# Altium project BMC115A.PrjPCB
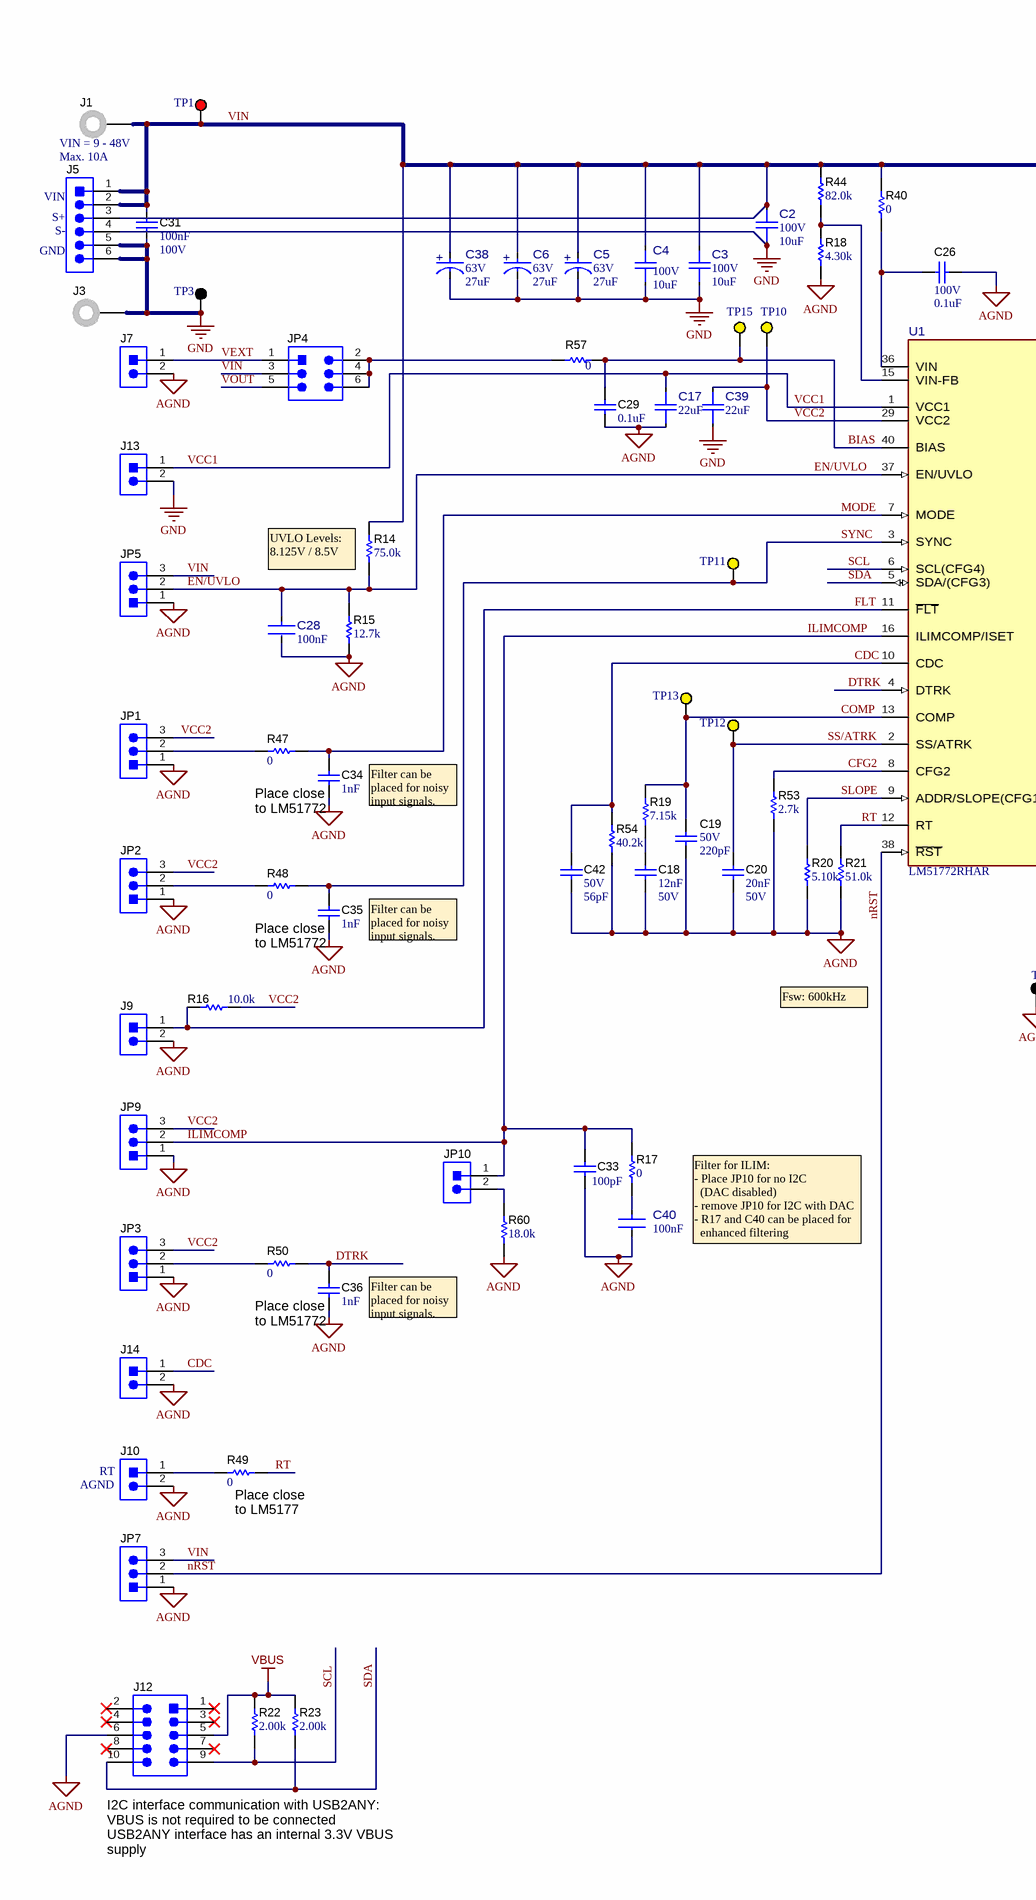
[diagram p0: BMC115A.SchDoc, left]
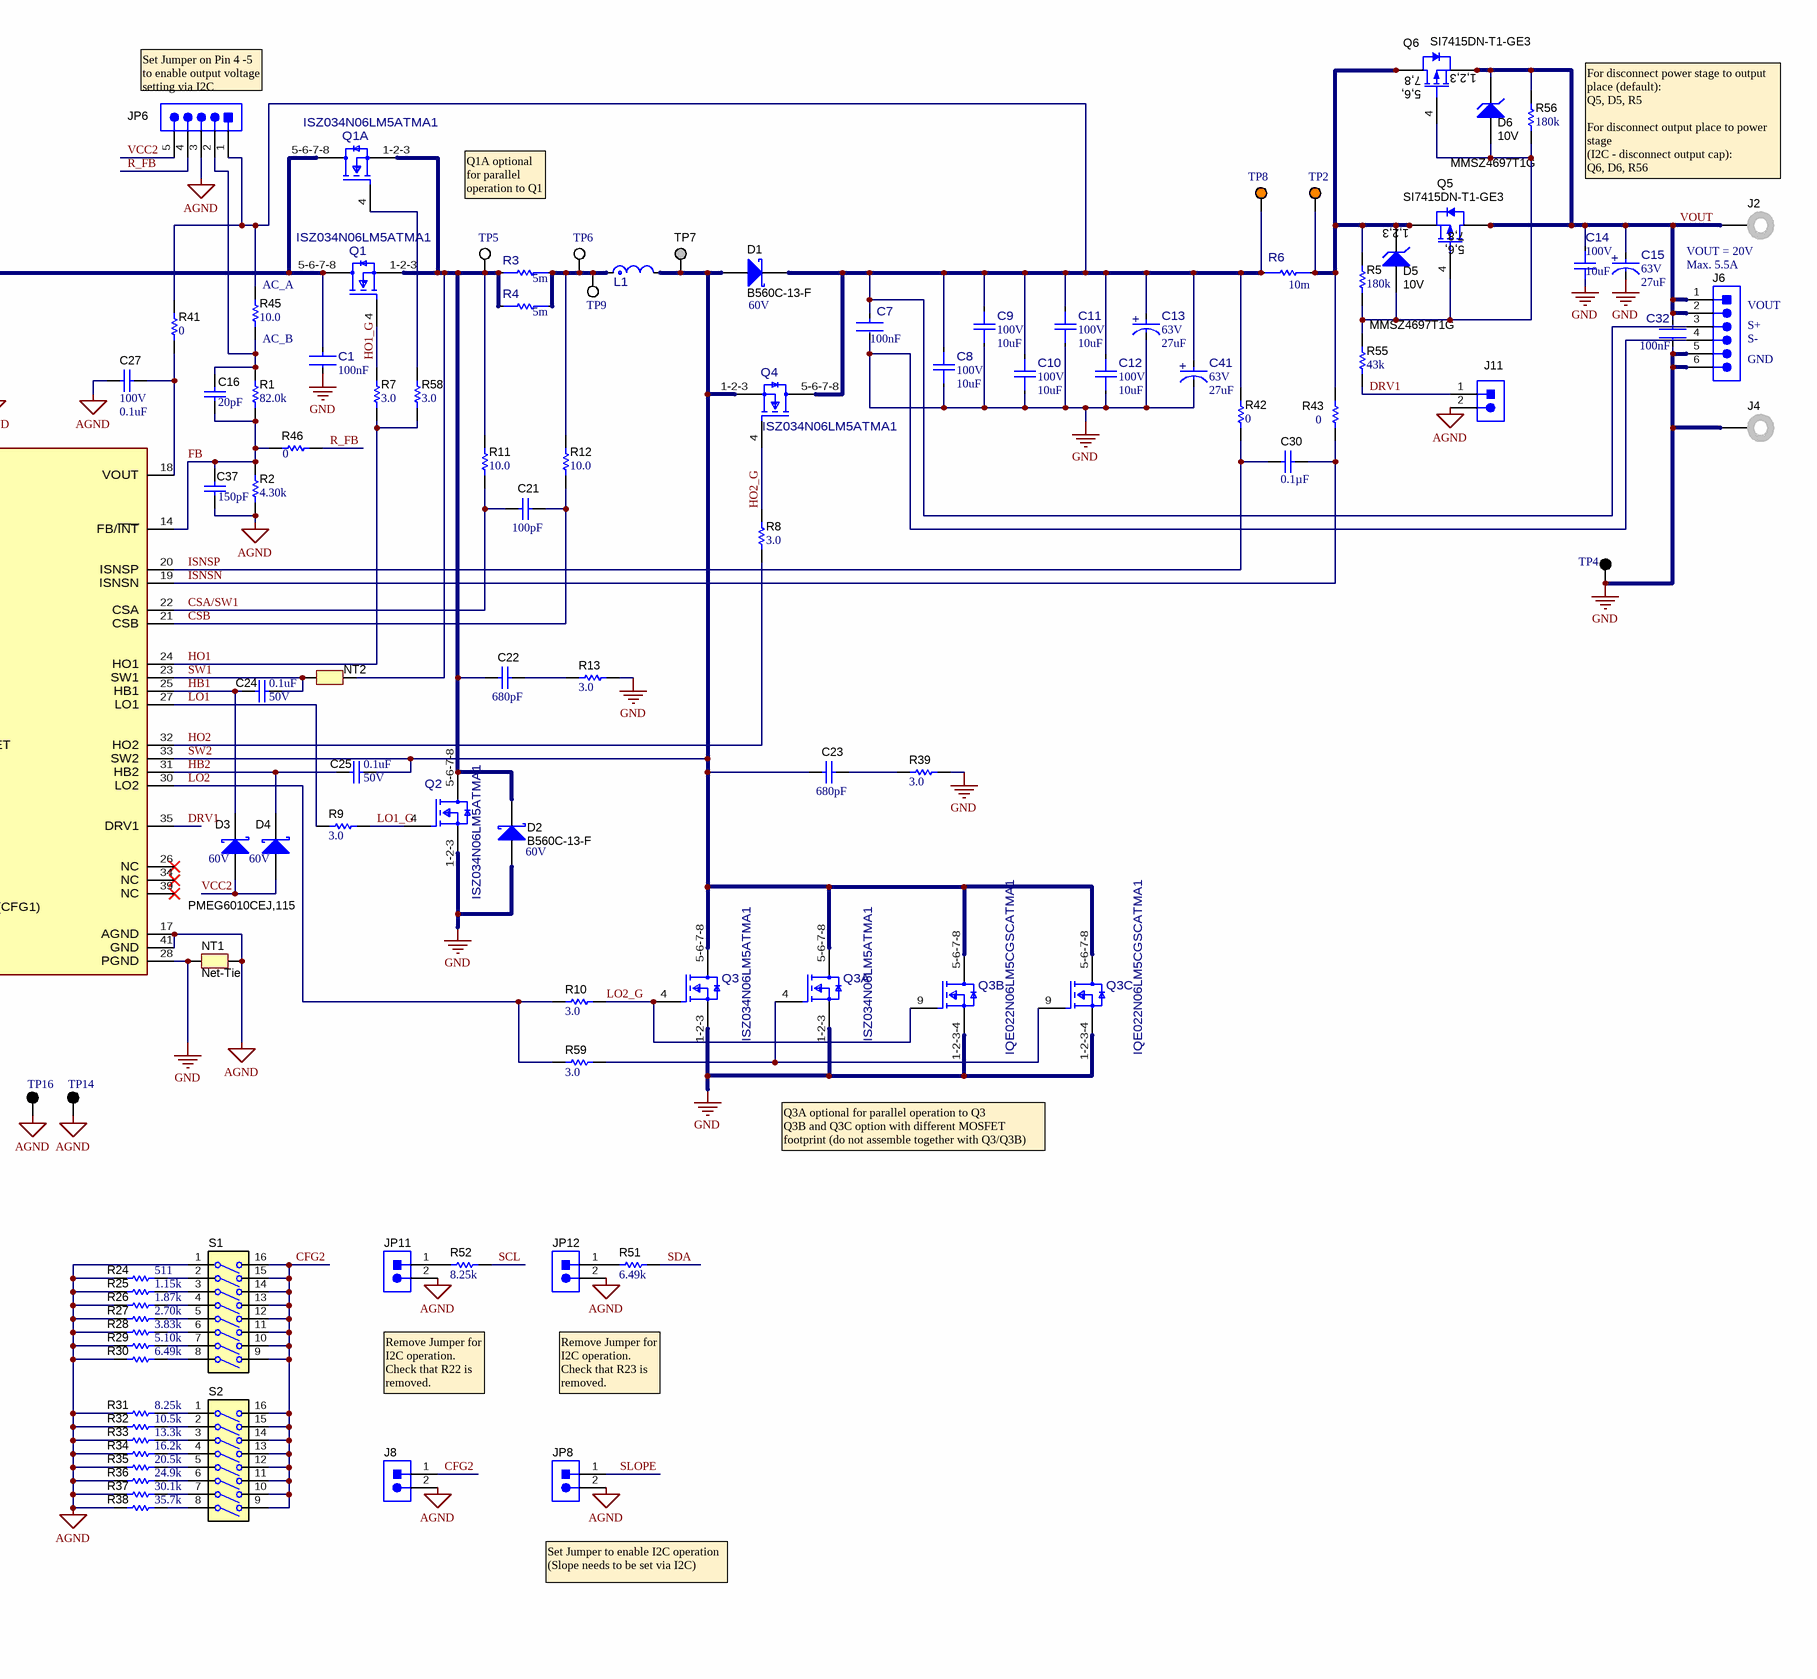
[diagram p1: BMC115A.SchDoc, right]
TID: N/A; TechSupport: http://www.ti.com/support; SCH_Rev: A; PRJ_Title: LM51772EVM-HP; PRJ_Number: BMC115; PRJ_Customer: Public Release; PCB_Rev: A; CopyrightYear: 2023
2 sheets, 200 parts. Net scope: global (net labels, ports and power ports of the same name join across sheets).
Board file: BMC115A.PcbDoc
Sheets:
  BMC115A.SchDoc
  BMC115A_Hardware.SchDoc

## Sheet BMC115A.SchDoc: LM51772RWE EVM Schematic
size 558 x 431 mm; Date: Not shown in title block; ApprovedBy: Not shown in title block; CheckedBy: Not shown in title block; Author: Not shown in title block; CompanyName: Not shown in title block; Engineer: Not shown in title block; Organization: Not shown in title block; Address1: Not shown in title block; Address2: Not shown in title block; Address3: Not shown in title block; Address4: Not shown in title block; DocumentNumber: 1; Revision: Use project parameter SCH_Rev; SheetNumber: 1; SheetTotal: 2; PageSetup: Record=PageOptions¦CenterHorizontal=True¦CenterVertical=True¦PrintScale=1.00¦XCorrection=1.00¦YCorrection=1.00¦PrintKind=0¦BorderSize=5000000¦LeftOffset=0¦BottomOffset=0¦Orientation=2¦PaperLength=1000¦PaperWidth=1000¦Scale=100¦PaperSource=15¦PrintQuality=600¦MediaType=1¦DitherType=10¦PaperKind=Letter¦PrintScaleMode=1

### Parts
C1  Cap_F: 100nF  [FP-GCM188L81H104KA57D_0603-MFG]  (hidden comment: GCM188L81H104KA57D)
C2  VDC_V: 100V  ValueDisplayed: 10uF  [FP-C3225X7R2A106K250AC_1210-MFG]  (hidden comment: C3225X7R2A106K250AC)
C3  VDC_V: 100V  ValueDisplayed: 10uF  [FP-C3225X7R2A106K250AC_1210-MFG]  (hidden comment: C3225X7R2A106K250AC)
C4  VDC_V: 100V  ValueDisplayed: 10uF  [FP-C3225X7R2A106K250AC_1210-MFG]  (hidden comment: C3225X7R2A106K250AC)
C5  VDC_V: 63V  ValueDisplayed: 27uF  [FP-A768KE276M1JLAE054_SMT_CAP_8MM3_8MM3-0]  (hidden comment: A768KE276M1JLAE054)
C6  VDC_V: 63V  ValueDisplayed: 27uF  [FP-A768KE276M1JLAE054_SMT_CAP_8MM3_8MM3-0]  (hidden comment: A768KE276M1JLAE054)
C7  Cap_F: 100nF  [FP-GCM188L81H104KA57D_0603-MFG]  (hidden comment: GCM188L81H104KA57D)
C8  VDC_V: 100V  ValueDisplayed: 10uF  [FP-C3225X7R2A106K250AC_1210-MFG]  (hidden comment: C3225X7R2A106K250AC)
C9  VDC_V: 100V  ValueDisplayed: 10uF  [FP-C3225X7R2A106K250AC_1210-MFG]  (hidden comment: C3225X7R2A106K250AC)
C10  VDC_V: 100V  ValueDisplayed: 10uF  [FP-C3225X7R2A106K250AC_1210-MFG]  (hidden comment: C3225X7R2A106K250AC)
C11  VDC_V: 100V  ValueDisplayed: 10uF  [FP-C3225X7R2A106K250AC_1210-MFG]  (hidden comment: C3225X7R2A106K250AC)
C12  VDC_V: 100V  ValueDisplayed: 10uF  [FP-C3225X7R2A106K250AC_1210-MFG]  (hidden comment: C3225X7R2A106K250AC)
C13  VDC_V: 63V  ValueDisplayed: 27uF  [FP-A768KE276M1JLAE054_SMT_CAP_8MM3_8MM3-0]  (hidden comment: A768KE276M1JLAE054)
C14  VDC_V: 100V  ValueDisplayed: 10uF  [FP-C3225X7R2A106K250AC_1210-MFG]  (hidden comment: C3225X7R2A106K250AC)
C15  VDC_V: 63V  ValueDisplayed: 27uF  [FP-A768KE276M1JLAE054_SMT_CAP_8MM3_8MM3-0]  (hidden comment: A768KE276M1JLAE054)
C16  ValueDisplayed: 20pF  [0603S]  (hidden comment: GRM1885C2A200JA01D)
C17  ValueDisplayed: 22uF  [0603S]  (hidden comment: GRT188R61A226ME13D)
C18  Cap_F: 12nF  VDC_V: 50V  [0603S]  (hidden comment: C0603C123K5RACTU)
C19  VDC_V: 50V  ValueDisplayed: 220pF  [0603S]  (hidden comment: 06035A221FAT2A)
C20  Cap_F: 20nF  VDC_V: 50V  [0603S]  (hidden comment: CC0603KRX7R9BB203)
C21  ValueDisplayed: 100pF  [0603S]  (hidden comment: GCM1885C1H101JA16J)
C22  ValueDisplayed: 680pF  [0805_HV1]  (hidden comment: GRM2195C2A681JA01D)
C23  ValueDisplayed: 680pF  [0805_HV1]  (hidden comment: GRM2195C2A681JA01D)
C24  VDC_V: 50V  ValueDisplayed: 0.1uF  [0402S]  (hidden comment: GCM155R71H104KE02D)
C25  VDC_V: 50V  ValueDisplayed: 0.1uF  [0402S]  (hidden comment: GCM155R71H104KE02D)
C26  VDC_V: 100V  ValueDisplayed: 0.1uF  [0402S]  (hidden comment: GRM155R62A104KE14D)
C27  VDC_V: 100V  ValueDisplayed: 0.1uF  [0402S]  (hidden comment: GRM155R62A104KE14D)
C28  Cap_F: 100nF  [FP-GCM188L81H104KA57D_0603-MFG]  (hidden comment: GCM188L81H104KA57D)
C29  ValueDisplayed: 0.1uF  [0603S]  (hidden comment: CGA3E3X7S2A104K080AB)
C30  ValueDisplayed: 0.1µF  [0402S]  (hidden comment: 0402BB104KW500)
C31  Cap_F: 100nF  VDC_V: 100V  [0603]  (hidden comment: GCJ188R72A104KA01D)
C32  Cap_F: 100nF  [FP-GCM188L81H104KA57D_0603-MFG]  (hidden comment: GCM188L81H104KA57D)
C33  ValueDisplayed: 100pF  [0603S]  (hidden comment: 06035A101FAT2A)
C34  Cap_F: 1nF  [0603S]  (hidden comment: 06031C102JAT2A)
C35  Cap_F: 1nF  [0603S]  (hidden comment: 06031C102JAT2A)
C36  Cap_F: 1nF  [0603S]  (hidden comment: 06031C102JAT2A)
C37  ValueDisplayed: 150pF  [0603S]  (hidden comment: GRM1885C1H151JA01D)
C38  VDC_V: 63V  ValueDisplayed: 27uF  [FP-A768KE276M1JLAE054_SMT_CAP_8MM3_8MM3-0]  (hidden comment: A768KE276M1JLAE054)
C39  ValueDisplayed: 22uF  [0603S]  (hidden comment: GRT188R61A226ME13D)
C40  Cap_F: 100nF  [FP-GCM188L81H104KA57D_0603-MFG]  (hidden comment: GCM188L81H104KA57D)
C41  VDC_V: 63V  ValueDisplayed: 27uF  [FP-A768KE276M1JLAE054_SMT_CAP_8MM3_8MM3-0]  (hidden comment: A768KE276M1JLAE054)
C42  VDC_V: 50V  ValueDisplayed: 56pF  [0603S]  (hidden comment: 06035A560FAT2A)
D1  B560C-13-F  value 60V  [SMC]
D2  B560C-13-F  value 60V  [SMC]
D3  value 60V  [SOD-323F]  (hidden comment: PMEG6010CEJ,115)
D4  PMEG6010CEJ,115  value 60V  [SOD-323F]
D5  MMSZ4697T1G  value 10V  [SOD-123]
D6  MMSZ4697T1G  value 10V  [SOD-123]
J1  108-0740-001  [Johnson_108-0740-001]  (value not drawn)
J2  108-0740-001  [Johnson_108-0740-001]  (value not drawn)
J3  108-0740-001  [Johnson_108-0740-001]  (value not drawn)
J4  108-0740-001  [Johnson_108-0740-001]  (value not drawn)
J5  61300611121  [WURTH_61300611121]  (value not drawn)
J6  61300611121  [WURTH_61300611121]  (value not drawn)
J7  61300211121  [WURTH_61300211121]  (value not drawn)
J8  61300211121  [WURTH_61300211121]  (value not drawn)
J9  61300211121  [WURTH_61300211121]  (value not drawn)
J10  61300211121  [WURTH_61300211121]  (value not drawn)
J11  61300211121  [WURTH_61300211121]  (value not drawn)
J12  N2510-6002-RB  [CONN_2510-6002]  (value not drawn)
J13  61300211121  [WURTH_61300211121]  (value not drawn)
J14  61300211121  [WURTH_61300211121]  (value not drawn)
JP1  61300311121  [WURTH_61300311121]  (value not drawn)
JP2  61300311121  [WURTH_61300311121]  (value not drawn)
JP3  61300311121  [WURTH_61300311121]  (value not drawn)
JP4  HTSW-103-07-G-D  [Samtec_HTSW-103-07-x-D]  (value not drawn)
JP5  61300311121  [WURTH_61300311121]  (value not drawn)
JP6  61300511121  [Wurth_61300511121]  (value not drawn)
JP7  61300311121  [WURTH_61300311121]  (value not drawn)
JP8  61300211121  [WURTH_61300211121]  (value not drawn)
JP9  61300311121  [WURTH_61300311121]  (value not drawn)
JP10  61300211121  [WURTH_61300211121]  (value not drawn)
JP11  61300211121  [WURTH_61300211121]  (value not drawn)
JP12  61300211121  [WURTH_61300211121]  (value not drawn)
L1  XGL1060-332MEC  [FP-XGL1060-332MEC_SMT2_10MM0_11MM3-MFG]  (value not drawn)
NT1  Net-Tie  [Net-Tie_10mil]  (net tie, no BOM)
NT2  Net-Tie  [Net-Tie_20milWide_60milLong]  (value not drawn)  (net tie, no BOM)
Q1  ISZ034N06LM5ATMA1  [FP-ISZ034N06LM5ATMA1_TSDSON8-MFG]
Q1A  ISZ034N06LM5ATMA1  [FP-ISZ034N06LM5ATMA1_TSDSON8-MFG]
Q2  ISZ034N06LM5ATMA1  [FP-ISZ034N06LM5ATMA1_TSDSON8-MFG]
Q3  ISZ034N06LM5ATMA1  [FP-ISZ034N06LM5ATMA1_TSDSON8-MFG]
Q3A  ISZ034N06LM5ATMA1  [FP-ISZ034N06LM5ATMA1_TSDSON8-MFG]
Q3B  IQE022N06LM5CGSCATMA1  [FP-IQE022N06LM5CGSCATMA1_PG-WHTFN-9-MFG]
Q3C  IQE022N06LM5CGSCATMA1  [FP-IQE022N06LM5CGSCATMA1_PG-WHTFN-9-MFG]
Q4  ISZ034N06LM5ATMA1  [FP-ISZ034N06LM5ATMA1_TSDSON8-MFG]
Q5  SI7415DN-T1-GE3  [PowerPAK_1212-8]
Q6  SI7415DN-T1-GE3  [PowerPAK_1212-8]
R1  ValueDisplayed: 82.0k  [0603S]  (hidden comment: RC0603FR-0782KL)
R2  ValueDisplayed: 4.30k  [0603S]  (hidden comment: RC0603FR-074K3L)
R3  value 5m  [FP-KRL2012E-M-R005-F-T5_0805_WIDE-MFG]  (hidden comment: KRL2012E-M-R005-F-T5)
R4  value 5m  [FP-KRL2012E-M-R005-F-T5_0805_WIDE-MFG]  (hidden comment: KRL2012E-M-R005-F-T5)
R5  ValueDisplayed: 180k  [0603S]  (hidden comment: CRCW0603180KJNEA)
R6  value 10m  [FP-KRL2012E-C-R010-F-T05_0508-MFG]  (hidden comment: KRL2012E-C-R010-F-T05)
R7  ValueDisplayed: 3.0  [0603S]  (hidden comment: CRCW06033R00JNEA)
R8  ValueDisplayed: 3.0  [0603S]  (hidden comment: CRCW06033R00JNEA)
R9  ValueDisplayed: 3.0  [0603S]  (hidden comment: CRCW06033R00JNEA)
R10  ValueDisplayed: 3.0  [0603S]  (hidden comment: CRCW06033R00JNEA)
R11  ValueDisplayed: 10.0  [0603S]  (hidden comment: CRCW060310R0FKEAHP)
R12  ValueDisplayed: 10.0  [0603S]  (hidden comment: CRCW060310R0FKEAHP)
R13  ValueDisplayed: 3.0  [0603S]  (hidden comment: CRCW06033R00JNEA)
R14  ValueDisplayed: 75.0k  [0603S]  (hidden comment: RC0603FR-0775KL)
R15  ValueDisplayed: 12.7k  [0603S]  (hidden comment: RC0603FR-0712K7L)
R16  ValueDisplayed: 10.0k  [0603S]  (hidden comment: RT0603BRD0710KL)
R17  ValueDisplayed: 0  [0603S]  (hidden comment: RMCF0603ZT0R00)
R18  ValueDisplayed: 4.30k  [0603S]  (hidden comment: RC0603FR-074K3L)
R19  ValueDisplayed: 7.15k  [0603S]  (hidden comment: CRCW06037K15FKEA)
R20  ValueDisplayed: 5.10k  [0603S]  (hidden comment: RC0603FR-075K1L)
R21  ValueDisplayed: 51.0k  [0603S]  (hidden comment: RC0603FR-0751KL)
R22  ValueDisplayed: 2.00k  [0603S]  (hidden comment: RC0603FR-072KL)
R23  ValueDisplayed: 2.00k  [0603S]  (hidden comment: RC0603FR-072KL)
R24  ValueDisplayed: 511  [0603S]  (hidden comment: CRCW0603511RFKEA)
R25  ValueDisplayed: 1.15k  [0603S]  (hidden comment: CRCW06031K15FKEA)
R26  ValueDisplayed: 1.87k  [0603S]  (hidden comment: RC0603FR-071K87L)
R27  ValueDisplayed: 2.70k  [0603S]  (hidden comment: RC0603FR-072K7L)
R28  ValueDisplayed: 3.83k  [0603S]  (hidden comment: CRCW06033K83FKEA)
R29  ValueDisplayed: 5.10k  [0603S]  (hidden comment: RC0603FR-075K1L)
R30  ValueDisplayed: 6.49k  [0603S]  (hidden comment: RC0603FR-076K49L)
R31  ValueDisplayed: 8.25k  [0603S]  (hidden comment: RC0603FR-078K25L)
R32  ValueDisplayed: 10.5k  [0603S]  (hidden comment: CRCW060310K5FKEA)
R33  ValueDisplayed: 13.3k  [0603S]  (hidden comment: RC0603FR-0713K3L)
R34  ValueDisplayed: 16.2k  [0603S]  (hidden comment: CRCW060316K2FKEA)
R35  ValueDisplayed: 20.5k  [0603S]  (hidden comment: RC0603FR-0720K5L)
R36  ValueDisplayed: 24.9k  [0603S]  (hidden comment: CRCW060324K9FKEA)
R37  ValueDisplayed: 30.1k  [0603S]  (hidden comment: CRCW060330K1FKEA)
R38  ValueDisplayed: 35.7k  [0603S]  (hidden comment: CRCW060335K7FKEA)
R39  ValueDisplayed: 3.0  [0603S]  (hidden comment: CRCW06033R00JNEA)
R40  ValueDisplayed: 0  [0603S]  (hidden comment: RMCF0603ZT0R00)
R41  ValueDisplayed: 0  [0603S]  (hidden comment: RMCF0603ZT0R00)
R42  ValueDisplayed: 0  [0603S]  (hidden comment: RMCF0603ZT0R00)
R43  ValueDisplayed: 0  [0603S]  (hidden comment: RMCF0603ZT0R00)
R44  ValueDisplayed: 82.0k  [0603S]  (hidden comment: RC0603FR-0782KL)
R45  ValueDisplayed: 10.0  [0603S]  (hidden comment: RC0603FR-0710RL)
R46  ValueDisplayed: 0  [0603S]  (hidden comment: RMCF0603ZT0R00)
R47  ValueDisplayed: 0  [0603S]  (hidden comment: RMCF0603ZT0R00)
R48  ValueDisplayed: 0  [0603S]  (hidden comment: RMCF0603ZT0R00)
R49  ValueDisplayed: 0  [0603S]  (hidden comment: RMCF0603ZT0R00)
R50  ValueDisplayed: 0  [0603S]  (hidden comment: RMCF0603ZT0R00)
R51  ValueDisplayed: 6.49k  [0603S]  (hidden comment: RC0603FR-076K49L)
R52  ValueDisplayed: 8.25k  [0603S]  (hidden comment: RC0603FR-078K25L)
R53  ValueDisplayed: 2.7k  [0603S]  (hidden comment: CRCW06032K70JNEA)
R54  ValueDisplayed: 40.2k  [0603S]  (hidden comment: CRCW060340K2FKEA)
R55  ValueDisplayed: 43k  [0603S]  (hidden comment: CRCW060343K0JNEA)
R56  ValueDisplayed: 180k  [0603S]  (hidden comment: CRCW0603180KJNEA)
R57  ValueDisplayed: 0  [0603S]  (hidden comment: RMCF0603ZT0R00)
R58  ValueDisplayed: 3.0  [0603S]  (hidden comment: CRCW06033R00JNEA)
R59  ValueDisplayed: 3.0  [0603S]  (hidden comment: CRCW06033R00JNEA)
R60  ValueDisplayed: 18.0k  [0603S]  (hidden comment: RC0603FR-0718KL)
S1  218-8LPST  [SW_218-8LP]  (value not drawn)
S2  218-8LPST  [SW_218-8LP]  (value not drawn)
TP1  5010  [Keystone5010]  (value not drawn)
TP2  5013  [Keystone5013]  (value not drawn)
TP3  5011  [Keystone5011]  (value not drawn)
TP4  5011  [Keystone5011]  (value not drawn)
TP5  5012  [Keystone5012]  (value not drawn)
TP6  5012  [Keystone5012]  (value not drawn)
TP7  5128  [Keystone5128]  (value not drawn)
TP8  5013  [Keystone5013]  (value not drawn)
TP9  5012  [Keystone5012]  (value not drawn)
TP10  5004  [Keystone5004]  (value not drawn)
TP11  5004  [Keystone5004]  (value not drawn)
TP12  5004  [Keystone5004]  (value not drawn)
TP13  5004  [Keystone5004]  (value not drawn)
TP14  5001  [Keystone5001]  (value not drawn)
TP15  5004  [Keystone5004]  (value not drawn)
TP16  5001  [Keystone5001]  (value not drawn)
U1  LM51772RHAR  [RHA0040P-MFG]

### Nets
AGND: C17.1 C18.2 C19.2 C20.2 C26.1 C27.2 C28.2 C29.1 C33.2 C34.2 C35.2 C36.2 C37.2 C40.2 C42.2 J7.2 J8.2 J9.2 J10.2 J11.2 J12.6 J14.2 JP1.1 JP2.1 JP3.1 JP5.1 JP6.3 JP7.1 JP8.2 JP9.1 JP11.2 JP12.2 NT1.2 R2.1 R15.1 R18.1 R20.1 R21.1 R24.1 R25.1 R26.1 R27.1 R28.1 R29.1 R30.1 R31.1 R32.1 R33.1 R34.1 R35.1 R36.1 R37.1 R38.1 R53.1 R54.1 R60.1 S1.1 TP14.1 TP16.1 U1.17(AGND) U1.41(GND)
GND: C1.2 C2.1 C3.1 C4.1 C5.1(CATHODE) C6.1(CATHODE) C7.2 C8.1 C9.1 C10.1 C11.1 C12.1 C13.1(CATHODE) C14.1 C15.1(CATHODE) C31.2 C32.2 C38.1(CATHODE) C39.1 C41.1(CATHODE) D2.2(A) J3.1 J4.1 J5.4 J5.5 J5.6 J6.4 J6.5 J6.6 J13.2 NT1.1 Q2.1-2-3(S) Q3.1-2-3(S) Q3A.1-2-3(S) Q3B.1-2-3-4(Source) Q3C.1-2-3-4(Source) R13.1 R39.1 TP3.1 TP4.1 U1.28(PGND)
VBUS: J12.5 R22.2 R23.2
BIAS: C29.2 R57.1 TP15.1 U1.40(BIAS)
CDC: C42.1 J14.1 R54.2 U1.10(CDC)
CFG2: J8.1 R53.2 S1.9(8A) S1.10(7A) S1.11(6A) S1.12(5A) S1.13(4A) S1.14(3A) S1.15(2A) S1.16(1A) S2.9(8A) S2.10(7A) S2.11(6A) S2.12(5A) S2.13(4A) S2.14(3A) S2.15(2A) S2.16(1A) U1.8(CFG2)
COMP: C19.1 R19.2 TP13.1 U1.13(COMP)
CSA/SW1: C21.2 R11.1 U1.22(CSA)
CSB: C21.1 R12.1 U1.21(CSB)
DRV1: J11.1 R55.1 U1.35(DRV1)
DTRK: C36.1 R50.2 U1.4(DTRK)
EN/UVLO: C28.1 JP5.2 R14.1 R15.2 U1.37(EN/UVLO)
FB: C16.2 C37.1 R1.1 R2.2 R46.1 U1.14(FB/~{INT})
FLT: J9.1 R16.1 U1.11(~{FLT})
HB1: C24.2 D3.1(K) U1.25(HB1)
HB2: C25.2 D4.1(K) U1.31(HB2)
HO1: R7.1 R58.1 U1.24(HO1)
HO1_G: Q1.4(G) R7.2
HO2: R8.1 U1.32(HO2)
HO2_G: Q4.4(G) R8.2
ILIMCOMP: C33.1 JP9.2 JP10.1 R17.2 U1.16(ILIMCOMP/ISET)
ISNSN: C30.1 R43.1 U1.19(ISNSN)
ISNSP: C30.2 R42.1 U1.20(ISNSP)
LO1: R9.2 U1.27(LO1)
LO1_G: Q2.4(G) R9.1
LO2: R10.2 R59.2 U1.30(LO2)
LO2_G: Q3.4(G) Q3B.9(Gate) R10.1
MODE: C34.1 R47.2 U1.7(MODE)
nRST: JP7.2 U1.38(~{RST})
R_FB: JP6.4 R46.2
RT: R21.2 R49.1 U1.12(RT)
SCL: J12.9 R22.1 R52.2 U1.6(SCL(CFG4))
SDA: J12.10 R23.1 R51.2 U1.5(SDA/(CFG3))
SLOPE: JP8.1 R20.2 U1.9(ADDR/SLOPE(CFG1))
SS/ATRK: C20.1 TP12.1 U1.2(SS/ATRK)
SW1: C24.1 NT2.1 U1.23(SW1)
SW2: C23.2 C25.1 D1.2(A) L1.2 Q3.5-6-7-8(D) Q3A.5-6-7-8(D) Q3B.5-6-7-8(Drain) Q3C.5-6-7-8(Drain) Q4.1-2-3(S) TP7.1 U1.33(SW2)
SYNC: C35.1 R48.2 TP11.1 U1.3(SYNC)
VCC1: C17.2 J13.1 U1.1(VCC1)
VCC2: C39.2 D3.2(A) D4.2(A) JP1.3 JP2.3 JP3.3 JP6.5 JP9.3 R16.2 TP10.1 U1.29(VCC2)
VEXT: J7.1 JP4.1
VIN: C1.1 C2.2 C3.2 C4.2 C5.2(ANODE) C6.2(ANODE) C31.1 C38.2(ANODE) J1.1 J5.1 J5.2 J5.3 JP4.3 JP5.3 JP7.3 Q1.5-6-7-8(D) Q1A.5-6-7-8(D) R14.2 R40.2 R44.2 TP1.1
VOUT: C14.2 C15.2(ANODE) C32.1 D6.1(K) J2.1 J6.1 J6.2 JP4.5 Q5.5(D) Q5.6(D) Q5.7(D) Q5.8(D) Q5.9(D) Q6.1(S) Q6.2(S) Q6.3(S) R56.2
NetC7_1: C7.1 C8.2 C9.2 C10.2 C11.2 C12.2 C13.2(ANODE) C41.2(ANODE) D1.1(K) J6.3 JP6.1 Q4.5-6-7-8(D) R6.1 R41.2 R42.2 R45.2 TP8.1
NetC16_1: C16.1 JP6.2 R1.2 R45.1
NetC18_1: C18.1 R19.1
NetC22_1: C22.1 R13.2
NetC22_2: C22.2 D2.1(K) NT2.2 Q1.1-2-3(S) Q1A.1-2-3(S) Q2.5-6-7-8(D) R3.2 R4.2 R11.2 TP5.1
NetC23_1: C23.1 R39.2
NetC26_2: C26.2 R40.1 U1.36(VIN)
NetC27_1: C27.1 R41.1 U1.18(VOUT)
NetC40_1: C40.1 R17.1
NetD5_1: D5.1(K) Q5.1(S) Q5.2(S) Q5.3(S) Q6.5(D) Q6.6(D) Q6.7(D) Q6.8(D) Q6.9(D) R5.2 R6.2 R43.2 TP2.1
NetD5_2: D5.2(A) D6.2(A) Q5.4(G) Q6.4(G) R5.1 R55.2 R56.1
NetJ10_1: J10.1 R49.2
NetJP1_2: JP1.2 R47.1
NetJP2_2: JP2.2 R48.1
NetJP3_2: JP3.2 R50.1
NetJP4_2: JP4.2 JP4.4 JP4.6 R57.2
NetJP10_2: JP10.2 R60.2
NetJP11_1: JP11.1 R52.1
NetJP12_1: JP12.1 R51.1
NetL1_1: L1.1 R3.1 R4.1 R12.2 TP6.1 TP9.1
NetQ1A_4: Q1A.4(G) R58.2
NetQ3A_4: Q3A.4(G) Q3C.9(Gate) R59.1
NetR18_2: R18.2 R44.1 U1.15(VIN-FB)
NetR24_2: R24.2 S1.2
NetR25_2: R25.2 S1.3
NetR26_2: R26.2 S1.4
NetR27_2: R27.2 S1.5
NetR28_2: R28.2 S1.6
NetR29_2: R29.2 S1.7
NetR30_2: R30.2 S1.8
NetR31_2: R31.2 S2.1
NetR32_2: R32.2 S2.2
NetR33_2: R33.2 S2.3
NetR34_2: R34.2 S2.4
NetR35_2: R35.2 S2.5
NetR36_2: R36.2 S2.6
NetR37_2: R37.2 S2.7
NetR38_2: R38.2 S2.8

Not connected (* = marked no-connect by the designer): J12 1* 2* 3* 4* 7* 8*; U1 26(NC)* 34(NC)* 39(NC)*

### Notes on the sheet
- (near JP6) Set Jumper on Pin 4 -5 to enable output voltage setting via I2C
- Q1A optional for parallel operation to Q1
- For disconnect power stage to output place (default):
  Q5, D5, R5
  For disconnect output place to power stage
  (I2C - disconnect output cap):
  Q6, D6, R56
- (near J1) VIN = 9 - 48V
- Max. 10A
- (near J2) VOUT = 20V
- Max. 5.5A
- (near J5) VIN
- (near J5) S+
- (near J5) S-
- (near R45) AC_A
- (near R45) AC_B
- (near J6) VOUT
- (near J6) S+
- (near J6) S-
- (near J5) GND
- (near J6) GND
- (near R14) UVLO Levels:
  8.125V / 8.5V
- (near C34) Place close
  to LM51772
- (near C34) Filter can be placed for noisy input signals.
- (near C35) Place close
  to LM51772
- (near C35) Filter can be placed for noisy input signals.
- Fsw: 600kHz
- Q3A optional for parallel operation to Q3
  Q3B and Q3C option with different MOSFET footprint (do not assemble together with Q3/Q3B)
- Filter for ILIM:
  - Place JP10 for no I2C
  (DAC disabled)
  - remove JP10 for I2C with DAC
  - R17 and C40 can be placed for
  enhanced filtering
- Filter can be placed for noisy input signals.
- Remove Jumper for I2C operation.
  Check that R22 is removed.
- Remove Jumper for I2C operation.
  Check that R23 is removed.
- (near C36) Place close
  to LM51772
- (near J10) AGND
- (near J10) RT
- (near R49) Place close
  to LM5177
- Set Jumper to enable I2C operation
  (Slope needs to be set via I2C)
- (near J12) I2C interface communication with USB2ANY:
  VBUS is not required to be connected
  USB2ANY interface has an internal 3.3V VBUS supply

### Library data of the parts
C1 C7 C28 C32 C40 = CMP-0086535-1: 0.1µF ±10% 50V Ceramic Capacitor X8L 0603 (1608 Metric); Manufacturer: Murata Electronics North America; Symbol Name: SYM-GCM188L81H104KA57D; AEC Qualified: Yes; TempCo: -40+15%; SizeZ_mm: 0.9mm; AEC Grade: Grade 0
C2-C4 C8-C12 C14 = CMP-0096021-1: 10 µF ±10% 100V Ceramic Capacitor X7R 1210 (3225 Metric); Manufacturer: TDK; Cap_F: 10µF; AEC Qualified: No; Value: 10µF; SizeZ_mm: 2.85mm; TempCo: 15%
C5 C6 C13 C15 C38 C41 = CMP-0097690-1: Cap Aluminum Polymer 27uF 63V 20% Solder Cylindrical 54m Ohm 1175mA 2000 hr 125°C T/R; Manufacturer: KEMET; Life: 2000Hours; Cap_F: 27µF; Value: 27µF; Leakage Current: 340uA; SizeZ_mm: 7mm; IRMS_A: 1.175A; AEC Qualified: No
C16 = CMP-0007253-4: CAP, CERM, 20 pF, 100 V, +/- 5%, C0G/NP0, 0603; Manufacturer: MuRata; TaMin_C: -55°C; Polarized: N; SizeAreaWB_mm2: 4.68; Value1: Unknown; U/M: EA; Value: 20pF; TaMax_C: 125°C; SizeZ_mm: 1; SizeX_mm: 1.6; SizeY_mm: 0.8; Cap_Case: 0603; Value2: 100V; SizeArea_mm2: 1.28; AEC Category: Q200
C17 C39 = CMP-0092433-2: Multi-Layer Ceramic Capacitor 22uF 10V X5R ±20% 0603 Paper T/R; Manufacturer: Murata; Cap_F: 22µF; Value: 22µF; SizeZ_mm: 1mm; AEC Qualified: Yes; AEC Grade: Grade 3; TempCo: 15%
C18 = CMP-0084236-1: CAP, CERM, 0.012 µF, 50 V,+/- 10%, X7R, AEC-Q200 Grade 1, 0603; Manufacturer: Kemet; TaMin_C: -55°C; Polarized: N; SizeAreaWB_mm2: 4.68; U/M: EA; Value: 0.012uF; TaMax_C: 125°C; SizeZ_mm: 1; SizeX_mm: 1.6; SizeY_mm: 0.8; Cap_Case: 0603; SizeArea_mm2: 1.28; AEC Qualified: Y; AEC Category: Q200
C19 = CMP-0006776-4: CAP, CERM, 220 pF, 50 V, +/- 1%, C0G/NP0, 0603; Manufacturer: AVX; TaMin_C: -55°C; ESR_ohm: 83m; Polarized: N; SizeAreaWB_mm2: 4.68; Value1: 0.083 ohm; U/M: EA; Value: 220pF; TaMax_C: 125°C; SizeZ_mm: 1; SizeX_mm: 1.6; SizeY_mm: 0.8; Cap_Case: 0603; SizeArea_mm2: 1.28; AEC Category: Q200
C20 = CMP-0086295-1: CAP, CERM, 0.02 µF, 50 V,+/- 10%, X7R, 0603; Manufacturer: Yageo; SizeX_mm: 1.6; SizeAreaWB_mm2: 4.68; TaMin_C: -55°C; SizeZ_mm: 1; SizeArea_mm2: 1.28; U/M: EA; Value: 0.02uF; Polarized: N; SizeY_mm: 0.8; TaMax_C: 125°C; Cap_Case: 0603; AEC Category: Q200; ValueDisplayed: 0.02µF
C21 = CMP-0750041-1: CAP, CERM, 100 pF, 50 V,+/- 5%, C0G/NP0, AEC-Q200 Grade 1, 0603; Manufacturer: MuRata; AEC Grade: 1; SizeArea_mm2: 1.28; SizeX_mm: 1.6; Polarized: N; Cap_Case: 0603; TaMax_C: 125°C; Value2: 50V; Value: 100pF; U/M: EA; AEC Qualified: Y; SizeAreaWB_mm2: 4.68; TaMin_C: -55°C; SizeY_mm: 0.8; AEC Category: Q200
C22 C23 = CMP-0008176-2: CAP, CERM, 680 pF, 100 V, +/- 5%, C0G/NP0, 0805; Manufacturer: MuRata; TaMin_C: -55°C; Polarized: N; SizeAreaWB_mm2: 6.75; Value1: Unknown; U/M: EA; Value: 680pF; TaMax_C: 125°C; SizeZ_mm: 1.45; SizeX_mm: 2; SizeY_mm: 1.25; Cap_Case: 0805; Value2: 100V; SizeArea_mm2: 2.5; AEC Category: Q200
C24 C25 = CMP-0006356-2: CAP, CERM, 0.1 uF, 50 V, +/- 10%, X7R, AEC-Q200 Grade 1, 0402; Manufacturer: MuRata; TaMin_C: -55°C; Polarized: N; SizeAreaWB_mm2: 3; Value1: Unknown; U/M: EA; Value: 0.1uF; TaMax_C: 125°C; SizeZ_mm: 0.6; SizeX_mm: 1; SizeY_mm: 0.5; Cap_Case: 0402; AEC Qualified: Y; Cap_F: 100nF; AEC Category: Q200
C26 C27 = CMP-0006618-2: CAP, CERM, 0.1 uF, 100 V, +/- 10%, X5R, 0402; Manufacturer: MuRata; TaMin_C: -55°C; Polarized: N; SizeAreaWB_mm2: 3; Value1: Unknown; U/M: EA; Value: 0.1uF; TaMax_C: 85°C; SizeZ_mm: 0.6; SizeX_mm: 1; SizeY_mm: 0.5; Cap_Case: 0402; Cap_F: 100nF; AEC Category: Q200
C29 = CMP-0007099-4: CAP, CERM, 0.1 uF, 100 V, +/- 10%, X7S, AEC-Q200 Grade 1, 0603; Manufacturer: TDK; TaMin_C: -55°C; ESR_ohm: 0.04959; Polarized: N; SizeAreaWB_mm2: 4.68; Value1: 0.04959 ohm; U/M: EA; Value: 0.1uF; TaMax_C: 125°C; SizeZ_mm: 1; SizeX_mm: 1.6; SizeY_mm: 0.8; Cap_Case: 0603; Value2: 100V; SizeArea_mm2: 1.28; AEC Qualified: Y; Cap_F: 100nF; IRMS_A: 7.51618dA; AEC Category: Q200
C30 = CMP-0860983-1: CAP, CERM, 0.1 µF, 50 V,+/- 10%, X7R, 0402; Manufacturer: Passive Plus; Cap_Case: 0402; TaMax_C: 125°C; VDC_V: 50V; U/M: EA; SizeY_mm: 0.5; TaMin_C: -55°C; SizeAreaWB_mm2: 3; Value: 0.1uF; AEC Qualified: N; SizeX_mm: 1; AEC Category: Q200; SizeZ_mm: 0.6; Cap_F: 100nF
C31 = CMP-0064935-4: CAP, CERM, 0.1 uF, 100 V,+/- 10%, X7R, AEC-Q200 Grade 1, 0603; Manufacturer: MuRata; TaMin_C: -55°C; Polarized: N; SizeAreaWB_mm2: 4.68; Value1: Unknown; U/M: EA; Value: 0.1uF; TaMax_C: 125°C; SizeZ_mm: 1; SizeX_mm: 1.6; SizeY_mm: 0.8; SizeArea_mm2: 1.28; AEC Qualified: Y; AEC Category: Q200
C33 = CMP-0006762-4: CAP, CERM, 100 pF, 50 V, +/- 1%, C0G/NP0, 0603; Manufacturer: AVX; TaMin_C: -55°C; Polarized: N; SizeAreaWB_mm2: 4.68; Value1: Unknown; U/M: EA; TaMax_C: 125°C; SizeZ_mm: 1; SizeX_mm: 1.6; SizeY_mm: 0.8; Cap_Case: 0603; Value2: 50V; SizeArea_mm2: 1.28; Value: 100pF; AEC Category: Q200
C34-C36 = CMP-0006723-4: CAP, CERM, 1000 pF, 100 V, +/- 5%, X7R, 0603; Manufacturer: AVX; TaMin_C: -55°C; ESR_ohm: 2.76d; Polarized: N; SizeAreaWB_mm2: 4.68; Value1: 0.276 ohm; U/M: EA; Value: 1000pF; TaMax_C: 125°C; SizeZ_mm: 1; SizeX_mm: 1.6; SizeY_mm: 0.8; Cap_Case: 0603; Value2: 100V; SizeArea_mm2: 1.28; AEC Category: Q200
C37 = CMP-0007185-4: CAP, CERM, 150 pF, 50 V, +/- 5%, C0G/NP0, 0603; Manufacturer: MuRata; TaMin_C: -55°C; Polarized: N; SizeAreaWB_mm2: 4.68; Value1: Unknown; U/M: EA; Value: 150pF; TaMax_C: 125°C; SizeZ_mm: 1; SizeX_mm: 1.6; SizeY_mm: 0.8; Cap_Case: 0603; Value2: 50V; SizeArea_mm2: 1.28; AEC Category: Q200
C42 = CMP-0006792-4: CAP, CERM, 56 pF, 50 V, +/- 1%, C0G/NP0, 0603; Manufacturer: AVX; TaMin_C: -55°C; Polarized: N; SizeAreaWB_mm2: 4.68; Value1: Unknown; U/M: EA; Value: 56pF; TaMax_C: 125°C; SizeZ_mm: 1; SizeX_mm: 1.6; SizeY_mm: 0.8; Cap_Case: 0603; SizeArea_mm2: 1.28; AEC Category: Q200
D1 D2 = CMP-0028433-2: Diode, Schottky, 60 V, 5 A, SMC; Manufacturer: Diodes Inc.; Io_A: 5A; Green_Lifecycle: Active; SizeAreaWB_mm2: 83.2686; Green_REACh: Passed; TJmax_C: 125°C; SizeZ_mm: 2.6; SizeX_mm: 8.13; SizeY_mm: 6.22; Vf_V: 700mV; Value2: 0.7V; SizeArea_mm2: 50.5686; AEC Category: Q101; RJC_CperW: 10
D3 D4 = CMP-0077011-2: Diode, Schottky, 60 V, 1 A, SOD-323F; Manufacturer: Nexperia; SizeX_mm: 2.5; TJmax_C: 150°C; SizeZ_mm: 0.8; Green_Lifecycle: Not Set; Value2: 0.66V; SizeAreaWB_mm2: 7.875; Green_REACh: Incomplete; Io_A: 1A; SizeY_mm: 1.25; SizeArea_mm2: 3.125; Vf_V: 660mV; AEC Category: Q101
D5 D6 = CMP-0005740-3: Diode, Zener, 10 V, 500 mW, SOD-123; Manufacturer: ON Semiconductor; SizeY_mm: 1.7; SizeX_mm: 3.85; RJA_CperW: 340; SizeAreaWB_mm2: 13.095; AEC Category: Q101; Power_W: 500mW; SizeZ_mm: 1.35; Value1: 0.5W; SizeArea_mm2: 6.545
J1-J4 = CMP-0055387-2: Standard Banana Jack, Uninsulated, 15A; Manufacturer: Cinch Connectivity; CNHeader: FALSE; Green_Lifecycle: Active; Green_REACh: Passed; CT: TRUE
J5 J6 = CMP-0054801-2: Header, 2.54 mm, 6x1, Gold, TH; Manufacturer: Wurth Elektronik; Cert_UL: Y; Gender: Male; Row_Count: 1; Shrouded: N; Pitch_mm: 2.54
J7-J11 J13 J14 JP8 JP10-JP12 = CMP-0054794-2: Header, 2.54 mm, 2x1, Gold, TH; Manufacturer: Wurth Elektronik; Shrouded: N; Gender: Male; Green_REACh: Passed; Pitch_mm: 2.54; Green_Lifecycle: Active; Row_Count: 1; Cert_UL: Y
J12 = CMP-0055448-2: Header (shrouded), 100mil, 5x2, High-Temperature, Gold, TH; Manufacturer: 3M; Green_Lifecycle: Active; Green_REACh: Passed
JP1-JP3 JP5 JP7 JP9 = CMP-0054796-4: Header, 2.54 mm, 3x1, Gold, TH; Manufacturer: Wurth Elektronik; Green_Lifecycle: Active; Green_REACh: Passed; CT: FALSE; CNHeader: TRUE
JP4 = CMP-0055587-2: Header, 2.54mm, 3x2, Gold, TH; Manufacturer: Samtec; Green_Lifecycle: Active; Shrouded: N; Gender: Male; Cert_CSA: Y; Green_REACh: Passed; Row_Count: 2; RowSpacing_mm: 2.54
JP6 = CMP-0084909-1: Header, 2.54mm, 5x1, Gold, TH; Manufacturer: Wurth Elektronik; Pitch_mm: 2.54; Current_A: 3A; Shrouded: N; Gender: Male; Voltage_V: 250V; Row_Count: 1
L1 = CMP-0097455-1: Shielded Power Inductors 3.3uH 22A 5.7mOhm; Manufacturer: Coilcraft; Isat: 10.9A; DCR_ohm: 5.7m; Ind_H: 3.3µH; Self Resonant Frequency: 21MHz; AEC Grade: Grade 1; SizeZ_mm: 6mm; Tolerance_%: 20%; TaMax_C: +125°C; AEC Qualified: Yes; TaMin_C: -40°C; Test Frequency: 1MHz; Material: Composite; Shrouded: true
NT1 NT2 = CMP-0078142-6: Single point connection between nets.
Q1 Q1A Q2 Q3 Q3A Q4 = CMP-0097450-1: N-Channel 60 V 19A (Ta), 112A (Tc) 2.5W (Ta), 83W (Tc) Surface Mount PG-TSDSON-8-26; Manufacturer: Infineon; Reverse Recovery Time: 20ns; Turn Off Delay Time: 27ns; Vgs_V: 20V; Threshold Vgs Min: 1.1V; TJmax_C: +175°C; Turn On Delay Time: 7.6ns; VdsMax_V: 1V; Pulse Drain Current: 448A; Rdson45_ohm: 2.9m; QgTyp_nC: 40nC @ 10V; Typ Forward Diode Voltage: 0.81V; Reverse Recovery Charge: 50nC; Rthja Max: 60°C/W; SizeZ_mm: 1mm; Transconductance: 80S; Threshold Vgs Max: 2.3V; Number Of Channels: 1; Input Capacitace At Vds: 2600pF @ 30V; AEC Qualified: No; Drain To Source Breakdown Voltage: 60V; ChMode: False
Q3B Q3C = CMP-0121112-1: MOSFET N-Channel 60 V 24A (Ta), 151A (Tc) 2.5W (Ta), 100W (Tc) Surface Mount PG-WHTFN-9; Manufacturer: Infineon; AEC Qualified: No; QgTyp_nC: 53nC @ 10V; Rdson45_ohm: 1.9m; SizeZ_mm: 0.75mm; VdsMax_V: 1V; Vgs_V: 20V; ChMode: False; Drain To Source Breakdown Voltage: 60V; Input Capacitace At Vds: 3400pF @ 30V; Number Of Channels: 1; Pulse Drain Current: 604A; Reverse Recovery Charge: 19nC; Reverse Recovery Time: 26ns; Rthja Max: 60°C/W; Threshold Vgs Max: 2.3V; Threshold Vgs Min: 1.1V; TJmax_C: +175°C; Transconductance: 93S; Turn On Delay Time: 6.1ns; Typ Forward Diode Voltage: 0.79V
Q5 Q6 = CMP-0000115-4: MOSFET, P-CH, -60 V, -3.6 A, PowerPAK 1212; Manufacturer: Vishay-Siliconix; Alternate Manufacturer: None; IdsMax_A: -3.6A; ChType: P; Vgs_V: -20V; Value1: 0.1; QgTyp_nC: 15; VdsMax_V: -60V; SizeAreaWB_mm2: 18.49; SizeX_mm: 3.3; ChMode: Enhancement; SizeArea_mm2: 10.89; Value: -60V; AEC Category: Q101; SizeZ_mm: 1.04; Rdson45_ohm: 0.11; Value2: 15 nC
R1 R44 = CMP-0023292-5: RES, 82.0 k, 1%, 0.1 W, 0603; Manufacturer: Yageo; Power_W: 100mW; TempCo: 100 ppm/C; Value_Code: 82k0; Value: 82.0k; Res_ohm: 82k; SizeX_mm: 1.6; SizeY_mm: 0.8; SizeZ_mm: 1; Value2: 0.1W; SizeArea_mm2: 1.28; AEC Qualified: N; VDC_V: 75V; AEC Category: Q200; SizeAreaWB_mm2: 4.68
R2 R18 = CMP-0023148-5: RES, 4.30 k, 1%, 0.1 W, 0603; Manufacturer: Yageo; Power_W: 100mW; TempCo: 100 ppm/C; Value_Code: 4k30; Value: 4.30k; Res_ohm: 4.3k; SizeX_mm: 1.6; SizeY_mm: 0.8; SizeZ_mm: 1; Value2: 0.1W; SizeArea_mm2: 1.28; AEC Qualified: N; VDC_V: 75V; AEC Category: Q200; SizeAreaWB_mm2: 4.68
R3 R4 = CMP-0090651-1: 5 mOhms ±1% 1W Chip Resistor Wide 0805 (2012 Metric), 0508 Automotive AEC-Q200, Current Sense Metal Foil; Manufacturer: Susumu; TempCo: 50ppm/°C; AEC Grade: Grade 0; AEC Qualified: Yes; SizeZ_mm: 0.7mm
R5 R56 = CMP-0025725-4: RES, 180 k, 5%, 0.1 W, AEC-Q200 Grade 0, 0603; Manufacturer: Vishay-Dale; Power_W: 100mW; TempCo: 200 ppm/C; Value: 180k; EIA_Code: E24; SizeX_mm: 1.6; SizeY_mm: 0.8; SizeZ_mm: 1; Value2: 0.1W; SizeArea_mm2: 1.28; AEC Qualified: Y; VDC_V: 75V; AEC Category: Q200; AEC Grade: 0
R6 = CMP-0097451-1: 10 mOhms ±1% 1W Chip Resistor Wide 0805 (2012 Metric), 0508 Automotive AEC-Q200, Current Sense Metal Foil; Manufacturer: Susumu; SizeZ_mm: 0.7mm; AEC Grade: Grade 0; AEC Qualified: Yes; TempCo: 50ppm/°C
R7-R10 R13 R39 R58 R59 = CMP-0025804-4: RES, 3.0, 5%, 0.1 W, AEC-Q200 Grade 0, 0603; Manufacturer: Vishay-Dale; Power_W: 100mW; TempCo: 200 ppm/C; Value_Code: 3R00; Value: 3.0; EIA_Code: E24; Res_ohm: 3; SizeX_mm: 1.6; SizeY_mm: 0.8; SizeZ_mm: 1; Value2: 0.1W; SizeArea_mm2: 1.28; AEC Qualified: Y; VDC_V: 75V; AEC Category: Q200; AEC Grade: 0
R11 R12 = CMP-0022004-4: RES, 10.0, 1%, 0.25 W, AEC-Q200 Grade 0, 0603; Manufacturer: Vishay-Dale; Power_W: 250mW; TempCo: 100 ppm/C; Value_Code: 10R0; Value: 10.0; EIA_Code: E96; Res_ohm: 10; SizeX_mm: 1.6; SizeY_mm: 0.8; SizeZ_mm: 1; Value2: 0.25W; SizeArea_mm2: 1.28; AEC Qualified: Y; VDC_V: 75V; AEC Category: Q200; AEC Grade: 0
R14 = CMP-0023267-5: RES, 75.0 k, 1%, 0.1 W, 0603; Manufacturer: Yageo; Power_W: 100mW; TempCo: 100 ppm/C; Value_Code: 75k0; Value: 75.0k; EIA_Code: E96; Res_ohm: 75k; SizeX_mm: 1.6; SizeY_mm: 0.8; SizeZ_mm: 1; Value2: 0.1W; SizeArea_mm2: 1.28; AEC Qualified: N; VDC_V: 75V; AEC Category: Q200; SizeAreaWB_mm2: 4.68
R15 = CMP-0022778-5: RES, 12.7 k, 1%, 0.1 W, 0603; Manufacturer: Yageo; Power_W: 100mW; TempCo: 100 ppm/C; Value_Code: 12k7; Value: 12.7k; EIA_Code: E96; SizeX_mm: 1.6; SizeY_mm: 0.8; SizeZ_mm: 1; Value2: 0.1W; SizeArea_mm2: 1.28; AEC Qualified: N; VDC_V: 75V; AEC Category: Q200; SizeAreaWB_mm2: 4.68
R16 = CMP-0023653-3: RES, 10.0 k, 0.1%, 0.1 W, 0603; Manufacturer: Yageo America; Power_W: 100mW; TempCo: 25 ppm/C; Value_Code: 10k0; U/M: EA; Value: 10.0k; EIA_Code: E192; Res_ohm: 10k; SizeX_mm: 1.6; SizeY_mm: 0.8; SizeZ_mm: 1; Value2: 0.1W; SizeArea_mm2: 1.28; VDC_V: 75V; AEC Category: Q200
R17 R40-R43 R46-R50 R57 = CMP-0023343-3: RES, 0, 1%, 0.1 W, AEC-Q200 Grade 0, 0603; Manufacturer: Stackpole Electronics Inc; Power_W: 100mW; TempCo: ppm/C; U/M: EA; Value: 0; SizeX_mm: 1.6; SizeY_mm: 0.8; SizeZ_mm: 1; Value2: 0.1W; SizeArea_mm2: 1.28; AEC Qualified: Y; AEC Category: Q200
R19 = CMP-0022599-4: RES, 7.15 k, 1%, 0.1 W, AEC-Q200 Grade 0, 0603; Manufacturer: Vishay-Dale; Power_W: 100mW; TempCo: 100 ppm/C; Value_Code: 7k15; Value: 7.15k; EIA_Code: E96; SizeX_mm: 1.6; SizeY_mm: 0.8; SizeZ_mm: 1; Value2: 0.1W; SizeArea_mm2: 1.28; AEC Qualified: Y; VDC_V: 75V; AEC Category: Q200; AEC Grade: 0
R20 R29 = CMP-0023198-5: RES, 5.10 k, 1%, 0.1 W, 0603; Manufacturer: Yageo; Power_W: 100mW; TempCo: 100 ppm/C; Value_Code: 5k10; Value: 5.10k; Res_ohm: 5.1k; SizeX_mm: 1.6; SizeY_mm: 0.8; SizeZ_mm: 1; Value2: 0.1W; SizeArea_mm2: 1.28; AEC Qualified: N; VDC_V: 75V; AEC Category: Q200; SizeAreaWB_mm2: 4.68
R21 = CMP-0023167-5: RES, 51.0 k, 1%, 0.1 W, 0603; Manufacturer: Yageo; Power_W: 100mW; TempCo: 100 ppm/C; Value_Code: 51k0; Value: 51.0k; Res_ohm: 51k; SizeX_mm: 1.6; SizeY_mm: 0.8; SizeZ_mm: 1; Value2: 0.1W; SizeArea_mm2: 1.28; AEC Qualified: N; VDC_V: 75V; AEC Category: Q200; SizeAreaWB_mm2: 4.68
R22 R23 = CMP-0023000-5: RES, 2.00 k, 1%, 0.1 W, 0603; Manufacturer: Yageo; Power_W: 100mW; TempCo: 100 ppm/C; Value_Code: 2k00; Value: 2.00k; EIA_Code: E96; Res_ohm: 2k; SizeX_mm: 1.6; SizeY_mm: 0.8; SizeZ_mm: 1; Value2: 0.1W; SizeArea_mm2: 1.28; AEC Qualified: N; VDC_V: 75V; AEC Category: Q200; SizeAreaWB_mm2: 4.68
R24 = CMP-0022481-5: RES, 511, 1%, 0.1 W, AEC-Q200 Grade 0, 0603; Manufacturer: Vishay-Dale; Power_W: 100mW; TempCo: 100 ppm/C; Value_Code: 511R; Value: 511; EIA_Code: E96; SizeX_mm: 1.6; SizeY_mm: 0.8; SizeZ_mm: 1; Value2: 0.1W; SizeArea_mm2: 1.28; AEC Qualified: Y; VDC_V: 75V; AEC Category: Q200; AEC Grade: 0
R25 = CMP-0022115-4: RES, 1.15 k, 1%, 0.1 W, AEC-Q200 Grade 0, 0603; Manufacturer: Vishay-Dale; Power_W: 100mW; TempCo: 100 ppm/C; Value_Code: 1k15; Value: 1.15k; EIA_Code: E96; SizeX_mm: 1.6; SizeY_mm: 0.8; SizeZ_mm: 1; Value2: 0.1W; SizeArea_mm2: 1.28; AEC Qualified: Y; VDC_V: 75V; AEC Category: Q200; AEC Grade: 0
R26 = CMP-0022891-5: RES, 1.87 k, 1%, 0.1 W, 0603; Manufacturer: Yageo; Power_W: 100mW; TempCo: 100 ppm/C; Value_Code: 1k87; Value: 1.87k; EIA_Code: E96; SizeX_mm: 1.6; SizeY_mm: 0.8; SizeZ_mm: 1; Value2: 0.1W; SizeArea_mm2: 1.28; AEC Qualified: N; VDC_V: 75V; AEC Category: Q200; SizeAreaWB_mm2: 4.68
R27 = CMP-0022996-5: RES, 2.70 k, 1%, 0.1 W, 0603; Manufacturer: Yageo; Power_W: 100mW; TempCo: 100 ppm/C; Value_Code: 2k70; Value: 2.70k; Res_ohm: 2.7k; SizeX_mm: 1.6; SizeY_mm: 0.8; SizeZ_mm: 1; Value2: 0.1W; SizeArea_mm2: 1.28; AEC Qualified: N; VDC_V: 75V; AEC Category: Q200; SizeAreaWB_mm2: 4.68
R28 = CMP-0022381-4: RES, 3.83 k, 1%, 0.1 W, AEC-Q200 Grade 0, 0603; Manufacturer: Vishay-Dale; Power_W: 100mW; TempCo: 100 ppm/C; Value_Code: 3k83; Value: 3.83k; EIA_Code: E96; SizeX_mm: 1.6; SizeY_mm: 0.8; SizeZ_mm: 1; Value2: 0.1W; SizeArea_mm2: 1.28; AEC Qualified: Y; VDC_V: 75V; AEC Category: Q200; AEC Grade: 0
R30 R51 = CMP-0023250-5: RES, 6.49 k, 1%, 0.1 W, 0603; Manufacturer: Yageo; Power_W: 100mW; TempCo: 100 ppm/C; Value_Code: 6k49; Value: 6.49k; EIA_Code: E96; SizeX_mm: 1.6; SizeY_mm: 0.8; SizeZ_mm: 1; Value2: 0.1W; SizeArea_mm2: 1.28; AEC Qualified: N; VDC_V: 75V; AEC Category: Q200; SizeAreaWB_mm2: 4.68
R31 R52 = CMP-0023307-5: RES, 8.25 k, 1%, 0.1 W, 0603; Manufacturer: Yageo; Power_W: 100mW; TempCo: 100 ppm/C; Value_Code: 8k25; Value: 8.25k; EIA_Code: E96; SizeX_mm: 1.6; SizeY_mm: 0.8; SizeZ_mm: 1; Value2: 0.1W; SizeArea_mm2: 1.28; AEC Qualified: N; VDC_V: 75V; AEC Category: Q200; SizeAreaWB_mm2: 4.68
R32 = CMP-0022000-4: RES, 10.5 k, 1%, 0.1 W, AEC-Q200 Grade 0, 0603; Manufacturer: Vishay-Dale; Power_W: 100mW; TempCo: 100 ppm/C; Value_Code: 10k5; Value: 10.5k; EIA_Code: E96; SizeX_mm: 1.6; SizeY_mm: 0.8; SizeZ_mm: 1; Value2: 0.1W; SizeArea_mm2: 1.28; AEC Qualified: Y; VDC_V: 75V; AEC Category: Q200; AEC Grade: 0
R33 = CMP-0022790-5: RES, 13.3 k, 1%, 0.1 W, 0603; Manufacturer: Yageo; Power_W: 100mW; TempCo: 100 ppm/C; Value_Code: 13k3; Value: 13.3k; EIA_Code: E96; SizeX_mm: 1.6; SizeY_mm: 0.8; SizeZ_mm: 1; Value2: 0.1W; SizeArea_mm2: 1.28; AEC Qualified: N; VDC_V: 75V; AEC Category: Q200; SizeAreaWB_mm2: 4.68
R34 = CMP-0022079-4: RES, 16.2 k, 1%, 0.1 W, AEC-Q200 Grade 0, 0603; Manufacturer: Vishay-Dale; Power_W: 100mW; TempCo: 100 ppm/C; Value_Code: 16k2; Value: 16.2k; EIA_Code: E96; SizeX_mm: 1.6; SizeY_mm: 0.8; SizeZ_mm: 1; Value2: 0.1W; SizeArea_mm2: 1.28; AEC Qualified: Y; VDC_V: 75V; AEC Category: Q200; AEC Grade: 0
R35 = CMP-0022905-5: RES, 20.5 k, 1%, 0.1 W, 0603; Manufacturer: Yageo; Power_W: 100mW; TempCo: 100 ppm/C; Value_Code: 20k5; Value: 20.5k; EIA_Code: E96; SizeX_mm: 1.6; SizeY_mm: 0.8; SizeZ_mm: 1; Value2: 0.1W; SizeArea_mm2: 1.28; AEC Qualified: N; VDC_V: 75V; AEC Category: Q200; SizeAreaWB_mm2: 4.68
R36 = CMP-0022237-4: RES, 24.9 k, 1%, 0.1 W, AEC-Q200 Grade 0, 0603; Manufacturer: Vishay-Dale; Power_W: 100mW; TempCo: 100 ppm/C; Value_Code: 24k9; Value: 24.9k; EIA_Code: E96; SizeX_mm: 1.6; SizeY_mm: 0.8; SizeZ_mm: 1; Value2: 0.1W; SizeArea_mm2: 1.28; AEC Qualified: Y; VDC_V: 75V; AEC Category: Q200; AEC Grade: 0
R37 = CMP-0022324-4: RES, 30.1 k, 1%, 0.1 W, AEC-Q200 Grade 0, 0603; Manufacturer: Vishay-Dale; Power_W: 100mW; TempCo: 100 ppm/C; Value_Code: 30k1; Value: 30.1k; EIA_Code: E96; SizeX_mm: 1.6; SizeY_mm: 0.8; SizeZ_mm: 1; Value2: 0.1W; SizeArea_mm2: 1.28; AEC Qualified: Y; VDC_V: 75V; AEC Category: Q200; AEC Grade: 0
R38 = CMP-0022352-4: RES, 35.7 k, 1%, 0.1 W, AEC-Q200 Grade 0, 0603; Manufacturer: Vishay-Dale; Power_W: 100mW; TempCo: 100 ppm/C; Value_Code: 35k7; Value: 35.7k; EIA_Code: E96; SizeX_mm: 1.6; SizeY_mm: 0.8; SizeZ_mm: 1; Value2: 0.1W; SizeArea_mm2: 1.28; AEC Qualified: Y; VDC_V: 75V; AEC Category: Q200; AEC Grade: 0
R45 = CMP-0022751-4: RES, 10.0, 1%, 0.1 W, 0603; Manufacturer: Yageo; Power_W: 100mW; TempCo: 100 ppm/C; Value_Code: 10R0; Value: 10.0; EIA_Code: E96; Res_ohm: 10; SizeX_mm: 1.6; SizeY_mm: 0.8; SizeZ_mm: 1; Value2: 0.1W; SizeArea_mm2: 1.28; AEC Qualified: N; VDC_V: 75V; AEC Category: Q200; SizeAreaWB_mm2: 4.68
R53 = CMP-0025771-4: RES, 2.7 k, 5%, 0.1 W, AEC-Q200 Grade 0, 0603; Manufacturer: Vishay-Dale; Power_W: 100mW; TempCo: 200 ppm/C; Value_Code: 2k70; Value: 2.7k; EIA_Code: E24; SizeX_mm: 1.6; SizeY_mm: 0.8; SizeZ_mm: 1; Value2: 0.1W; SizeArea_mm2: 1.28; AEC Qualified: Y; VDC_V: 75V; AEC Category: Q200; AEC Grade: 0
R54 = CMP-0022410-4: RES, 40.2 k, 1%, 0.1 W, AEC-Q200 Grade 0, 0603; Manufacturer: Vishay-Dale; Power_W: 100mW; TempCo: 100 ppm/C; Value_Code: 40k2; Value: 40.2k; EIA_Code: E96; SizeX_mm: 1.6; SizeY_mm: 0.8; SizeZ_mm: 1; Value2: 0.1W; SizeArea_mm2: 1.28; AEC Qualified: Y; VDC_V: 75V; AEC Category: Q200; AEC Grade: 0
R55 = CMP-0025810-4: RES, 43 k, 5%, 0.1 W, AEC-Q200 Grade 0, 0603; Manufacturer: Vishay-Dale; Power_W: 100mW; TempCo: 200 ppm/C; Value_Code: 43k0; Value: 43k; EIA_Code: E24; SizeX_mm: 1.6; SizeY_mm: 0.8; SizeZ_mm: 1; Value2: 0.1W; SizeArea_mm2: 1.28; AEC Qualified: Y; VDC_V: 75V; AEC Category: Q200; AEC Grade: 0
R60 = CMP-0022852-5: RES, 18.0 k, 1%, 0.1 W, 0603; Manufacturer: Yageo; Power_W: 100mW; TempCo: 100 ppm/C; Value_Code: 18k0; Value: 18.0k; Res_ohm: 18k; SizeX_mm: 1.6; SizeY_mm: 0.8; SizeZ_mm: 1; Value2: 0.1W; SizeArea_mm2: 1.28; AEC Qualified: N; VDC_V: 75V; AEC Category: Q200; SizeAreaWB_mm2: 4.68
S1 S2 = CMP-0002229-1: Switch, SPST, 8 Pos, 25mA, 24VDC, SMD; Manufacturer: CTS Electrocomponents; CurrentRating_mA: 25A; PositionCount: 8; VDC_V: 24V; SwitchFunction: Off-On
TP1 = CMP-0055147-2: Test Point, Multipurpose, Red, TH; Manufacturer: Keystone Electronics; CNHeader: FALSE; Green_Lifecycle: Active; Green_REACh: Passed; ContactFinish: Silver; CT: TRUE
TP2 TP8 = CMP-0055150-2: Test Point, Multipurpose, Orange, TH; Manufacturer: Keystone Electronics; CNHeader: FALSE; Green_Lifecycle: Active; Green_REACh: Passed; ContactFinish: Silver; CT: TRUE
TP3 TP4 = CMP-0055148-2: Test Point, Multipurpose, Black, TH; Manufacturer: Keystone Electronics; CNHeader: FALSE; Green_Lifecycle: Active; Green_REACh: Passed; ContactFinish: Silver; CT: TRUE
TP5 TP6 TP9 = CMP-0055149-2: Test Point, Multipurpose, White, TH; Manufacturer: Keystone Electronics; CNHeader: FALSE; Green_Lifecycle: Active; Green_REACh: Passed; ContactFinish: Silver; CT: TRUE
TP7 = CMP-0055159-2: Test Point, Multipurpose, Grey, TH; Manufacturer: Keystone Electronics; CNHeader: FALSE; Green_Lifecycle: Active; Green_REACh: Passed; ContactFinish: Silver; CT: TRUE
TP10-TP13 TP15 = CMP-0055141-2: Test Point, Miniature, Yellow, TH; Manufacturer: Keystone Electronics; CNHeader: FALSE; Green_Lifecycle: Active; Green_REACh: Passed; ContactFinish: Silver; CT: TRUE
TP14 TP16 = CMP-0055138-2: Test Point, Miniature, Black, TH; Manufacturer: Keystone Electronics; CNHeader: FALSE; Green_Lifecycle: Active; Green_REACh: Passed; ContactFinish: Silver; CT: TRUE
U1 = CMP-0120007-1: 48-V 4 Switch Buck-Boost Controller with I2C interface; Manufacturer: Texas Instruments; SizeZ_mm: 1mm; AEC Qualified: No; Max Supply Voltage: 48V; Min Supply Voltage: 3.3V; Nominal Supply Current: 25uA; Number Of Outputs: 1; Output Type: AdjustableProgrammable; Output Voltage: 3.3-48V; Standoff Height: 0mm; Switching Frequency: 100-2200kHz; Switching Topology: Boost,Buck,Buck-Boost; TJmax_C: +150°C

## Sheet BMC115A_Hardware.SchDoc: LM51772RWE EVM Hardware
size 431 x 279 mm; Date: Not shown in title block; ApprovedBy: Not shown in title block; CheckedBy: Not shown in title block; Author: Not shown in title block; CompanyName: Not shown in title block; Engineer: Not shown in title block; Organization: Not shown in title block; Address1: Not shown in title block; Address2: Not shown in title block; Address3: Not shown in title block; Address4: Not shown in title block; DocumentNumber: 3; Revision: Use project parameter SCH_Rev; SheetNumber: 2; SheetTotal: 2; PageSetup: Record=PageOptions¦CenterHorizontal=True¦CenterVertical=True¦PrintScale=1.00¦XCorrection=1.00¦YCorrection=1.00¦PrintKind=0¦BorderSize=5000000¦LeftOffset=0¦BottomOffset=0¦Orientation=2¦PaperLength=1000¦PaperWidth=1000¦Scale=100¦PaperSource=15¦PrintQuality=600¦MediaType=1¦DitherType=10¦PaperKind=Letter¦PrintScaleMode=1
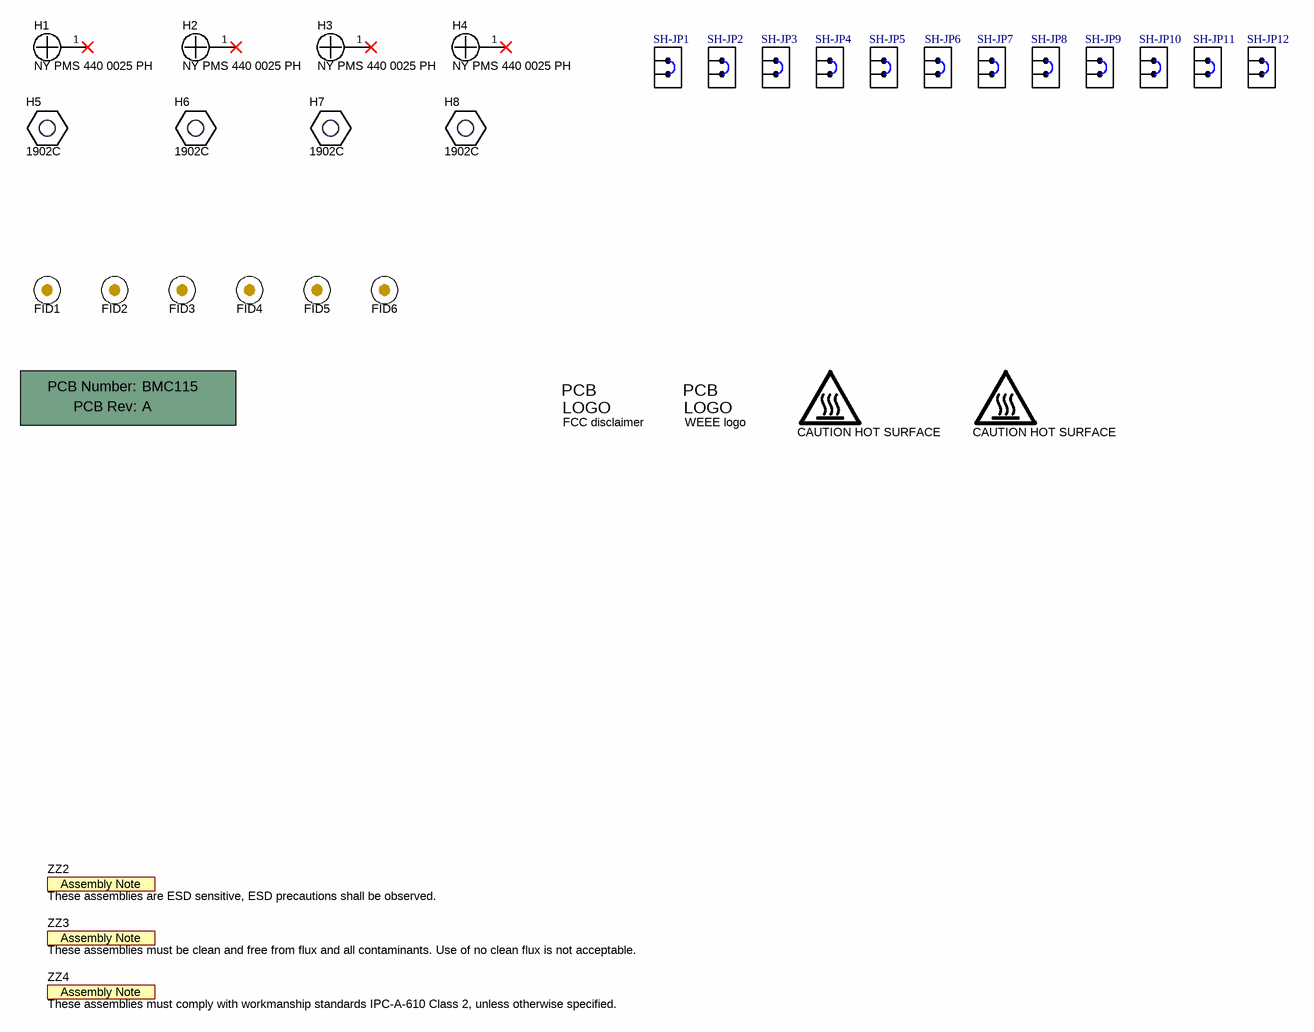
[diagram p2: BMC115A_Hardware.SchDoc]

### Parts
!PCB  Printed Circuit Board  (value not drawn)  (mechanical)
FID1  Fiducial  [Fiducial10-20]  (value not drawn)
FID2  Fiducial  [Fiducial10-20]  (value not drawn)
FID3  Fiducial  [Fiducial10-20]  (value not drawn)
FID4  Fiducial  [Fiducial10-20]  (value not drawn)
FID5  Fiducial  [Fiducial10-20]  (value not drawn)
FID6  Fiducial  [Fiducial10-20]  (value not drawn)
H1  NY PMS 440 0025 PH  [NY PMS 440 0025 PH]
H2  NY PMS 440 0025 PH  [NY PMS 440 0025 PH]
H3  NY PMS 440 0025 PH  [NY PMS 440 0025 PH]
H4  NY PMS 440 0025 PH  [NY PMS 440 0025 PH]
H5  1902C  [Keystone_1902C]
H6  1902C  [Keystone_1902C]
H7  1902C  [Keystone_1902C]
H8  1902C  [Keystone_1902C]
Logo3  FCC disclaimer  [FCC_disclaimer]  (no BOM)
Logo4  WEEE logo  [WEEE_Minimum]  (no BOM)
Logo5  CAUTION HOT SURFACE  [IEC_HotSurface_Small]  (no BOM)
Logo6  CAUTION HOT SURFACE  [IEC_HotSurface_Small]  (no BOM)
SH-JP1  M7582-05  [Harwin_M7582-05]  (value not drawn)
SH-JP2  M7582-05  [Harwin_M7582-05]  (value not drawn)
SH-JP3  M7582-05  [Harwin_M7582-05]  (value not drawn)
SH-JP4  M7582-05  [Harwin_M7582-05]  (value not drawn)
SH-JP5  M7582-05  [Harwin_M7582-05]  (value not drawn)
SH-JP6  M7582-05  [Harwin_M7582-05]  (value not drawn)
SH-JP7  M7582-05  [Harwin_M7582-05]  (value not drawn)
SH-JP8  M7582-05  [Harwin_M7582-05]  (value not drawn)
SH-JP9  M7582-05  [Harwin_M7582-05]  (value not drawn)
SH-JP10  M7582-05  [Harwin_M7582-05]  (value not drawn)
SH-JP11  M7582-05  [Harwin_M7582-05]  (value not drawn)
SH-JP12  M7582-05  [Harwin_M7582-05]  (value not drawn)
ZZ2  These assemblies are ESD sensitive, ESD precautions shall be observed.  [AssemblyNote]  (no BOM)
ZZ3  These assemblies must be clean and free from flux and all contaminants. Use of no clean flux is not acceptable.  [AssemblyNote]  (no BOM)
ZZ4  These assemblies must comply with workmanship standards IPC-A-610 Class 2, unless otherwise specified.  [AssemblyNote]  (no BOM)

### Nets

Not connected (* = marked no-connect by the designer): H1 1*; H2 1*; H3 1*; H4 1*

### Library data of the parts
!PCB = CMP-0003618-2: Manufacturer: Any; PartNumber: BMC115
FID1-FID6 = CMP-0077181-1: Fiducial mark.  There is nothing to buy or mount.
H1-H4 = CMP-0003617-1: Machine Screw, Round, #4-40 x 1/4, Nylon, Philips panhead; Manufacturer: B&F Fastener Supply; CompType: Hardware
H5-H8 = CMP-0003610-1: Standoff, Hex, 0.5"L #4-40 Nylon; Manufacturer: Keystone; CompType: Hardware
Logo3 = CMP-0074847-1: FCC_disclaimer; Library Reference: Logo
Logo4 = CMP-0074769-3: Manufacturer: Texas Instruments; CompType: IC; AEC Category: Q200
Logo5 Logo6 = CMP-0074837-2: IEC 61010-1 Hot Surface Warning; Manufacturer: Texas Instruments; SymbolCreator: a0412235; CompType: IC; AEC Category: Q200
SH-JP1-SH-JP12 = CMP-0078738-1: Single Operation 2.54mm Pitch Open Top Jumper Socket; Manufacturer: Harwin
ZZ2 = CMP-0077236-1
ZZ3 = CMP-0077237-1
ZZ4 = CMP-0077238-1

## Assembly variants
001: not fitted C4 C16 C30 C34 C35 C36 C37 C40 C41 D1 D2 D3 D4 D6 FID1 FID2 FID3 FID4 FID5 FID6 H1 H2 H3 H4 H5 H6 H7 H8 Q1A Q3A Q3B Q3C Q6 R17 R22 R23 R53 R56 R58 R59 SH-JP5 SH-JP6 SH-JP8 TP6 TP12 TP13 TP14 TP15 TP16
